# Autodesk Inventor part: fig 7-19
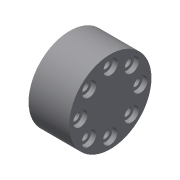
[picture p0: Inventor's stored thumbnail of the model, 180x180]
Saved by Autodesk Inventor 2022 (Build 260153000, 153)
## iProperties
Created: 2004-05
Part Number: fig 7-19
Document SubType Name: Modeling
Designer: CADCIM Technologies
Manufacturer: Standard
Standards Organization: Custom
Density: 1 g/cm^3
Material: Generic
Appearance: Default
Author: CADCIM Technologies
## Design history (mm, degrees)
sketch "Sketch1"
  geometry: C1 r 17.175 at (0, 0)
  constraints: 1 centre point
extrude "Extrusion1" new body sketch "Sketch1" distance "d0" = 17; taper "d1" = 0 deg
sketch "Sketch2"
  geometry: 1 further point
hole "Hole1" sketch "Sketch2" at (12.571, -0.074) diameter "d2" = 3.5; stored, may be unused: countersink angle "d6" = 90 deg, drill point angle "d8" = 118 deg; dims "d3" = 6, "d4" = 6, "d5" = 2, "d7" = 8
pattern_circular "Circular Pattern1" dims angle "d11" = 360 deg
body "Solid1"
